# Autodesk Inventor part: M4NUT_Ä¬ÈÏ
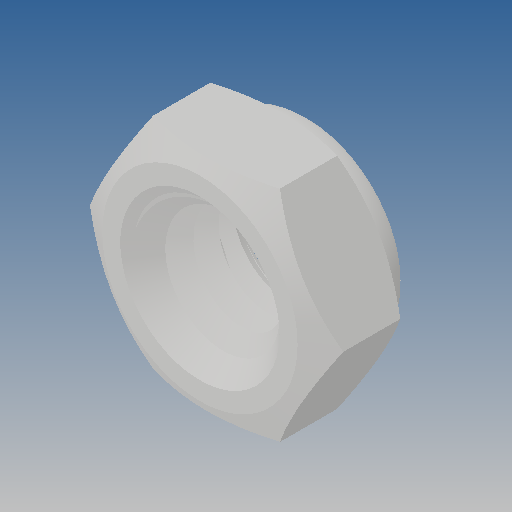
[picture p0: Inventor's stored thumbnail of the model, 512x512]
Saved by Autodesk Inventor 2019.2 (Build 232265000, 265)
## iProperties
Created: 2010-06
Part Number: M4NUT_Ä¬ÈÏ
Material: Ogólny
Document SubType Name: Modeling
Designer: CADENGINEERING4
Density: 1 g/cm^3
Appearance: Domyślna
Author: CADENGINEERING4
Revision Number: ÈÎºÎ
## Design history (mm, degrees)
feature "NONE"
node "Bryła1"
